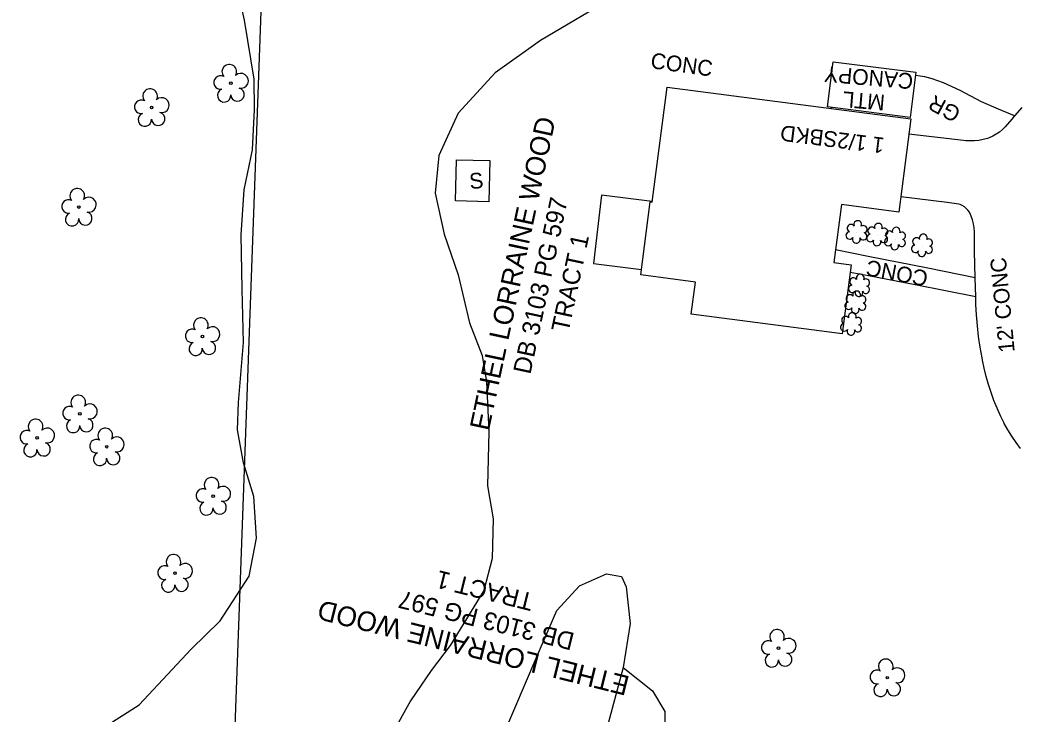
# Model space of a CAD drawing. Extents: x 1614611 to 1617571, y 898867 to 905462.
# Drawn here: x 1616188.4 to 1616442, y 900981.3 to 901157.4 of the extents above; entities that cross this region are included whole.
import ezdxf

# ---------------------------------------------------------------- set-up
doc = ezdxf.new("R2010")
doc.units = 0
for name, color, linetype in [('Exist Building', 7, 'Continuous'), ('Exist Building Metal Canopy', 7, 'Continuous'), ('Exist Building Metal Canopy Text', 7, 'Continuous'), ('Exist Building Text', 7, 'Continuous'), ('Exist Other Culture Area Outline', 7, 'Continuous'), ('Exist Other Culture Area Outline Text', 7, 'Continuous'), ('Exist Roads EOP Other Text', 7, 'Continuous'), ('Exist Roads Soil', 7, 'Continuous'), ('Exist Roads Soil Text', 7, 'Continuous'), ('Exist Vegetation Hedge Row', 7, 'Continuous'), ('Exist Vegetation Shrub CELL', 7, 'Continuous'), ('Exist Vegetation Tree CELL', 7, 'Continuous'), ('Exist Vegetation Woods Line', 7, 'Continuous'), ('Prop Drainage Structure Pipe Alternate 30in Label', 7, 'Continuous'), ('Prop Drainage Structure Pipe Removal', 7, 'Continuous'), ('Prop Drainage Structure Pipe Removal Label', 7, 'Continuous'), ('Scratch_Level_1', 7, 'Continuous')]:
    doc.layers.add(name, color=color, linetype=linetype)

msp = doc.modelspace()

# ---------------------------------------------------------------- linework, layer by layer
at = {"layer": 'Exist Building'}
for points in [[(1616396.84, 901077.74), (1616358.59, 901082.71), (1616359.65, 901090.88), (1616345.81, 901092.68), (1616348.22, 901111.22), (1616348.7, 901111.16), (1616352.48, 901140.3), (1616414.28, 901132.27), (1616411.21, 901108.63), (1616396.69, 901110.52), (1616394.79, 901095.84), (1616399.12, 901095.28)], [(1616307.51, 901121.72), (1616307.26, 901111.26), (1616298.82, 901111.46), (1616299.07, 901121.92)]]:
    msp.add_lwpolyline(points, close=True, dxfattribs=at)
at = {"layer": 'Exist Building Metal Canopy'}
msp.add_lwpolyline([(1616394.62, 901146.76), (1616415.59, 901144.12), (1616414.15, 901132.66), (1616393.18, 901135.29)], close=True, dxfattribs=at)
at = {"layer": 'Exist Other Culture Area Outline'}
for points in [[(1616348.72, 901111.35), (1616335.84, 901112.95), (1616334.83, 901104.27), (1616333.79, 901095.59), (1616345.99, 901094.11)], [(1616430.62, 901091.98), (1616418.63, 901094.43), (1616403.51, 901097.39), (1616395.21, 901099.09)], [(1616430.73, 901087.1), (1616415.4, 901090.19), (1616403.56, 901092.48), (1616398.87, 901093.33)]]:
    msp.add_lwpolyline(points, dxfattribs=at)
at = {"layer": 'Exist Roads Soil'}
for points in [[(1616440.58, 901133.01), (1616436.48, 901134.71), (1616432.24, 901136.61), (1616426.81, 901139.47), (1616422.54, 901141.46), (1616419.7, 901142.46), (1616417.85, 901142.91), (1616415.49, 901143.31)], [(1616394.15, 901135.17), (1616394.11, 901134.89)]]:
    msp.add_lwpolyline(points, dxfattribs=at)
at = {"layer": 'Exist Vegetation Hedge Row'}
msp.add_lwpolyline([(1616341.37, 900993.14), (1616348.75, 900987.2), (1616351.92, 900981.98), (1616351.91, 900977.26)], dxfattribs=at)
at = {"layer": 'Exist Vegetation Shrub CELL'}
for p, q in [((1616400.59, 901103.42), (1616400.59, 901103.42)), ((1616405.83, 901102.75), (1616405.83, 901102.75)), ((1616410.34, 901101.75), (1616410.34, 901101.75)), ((1616417.2, 901100.03), (1616417.2, 901100.03)), ((1616401.24, 901089.87), (1616401.24, 901089.87)), ((1616400.31, 901085.59), (1616400.31, 901085.59)), ((1616399.21, 901080.09), (1616399.21, 901080.09))]:
    msp.add_line(p, q, dxfattribs=at)
for centre, radius, start, end in [((1616399.11, 901104.54), 0.968, 35.8908, 245.4216), ((1616400.82, 901105.46), 0.99, 334.8391, 200.4717), ((1616406.06, 901104.79), 0.99, 334.8391, 200.4717), ((1616398.79, 901102.71), 0.955, 95.1099, 327.9534), ((1616402.23, 901102.49), 0.937, 204.9913, 73.4601), ((1616402.26, 901104.28), 0.929, 284.4567, 126.0861), ((1616404.03, 901102.05), 0.955, 95.1099, 327.9534), ((1616404.35, 901103.88), 0.968, 35.8908, 245.4216), ((1616407.5, 901103.62), 0.929, 284.4567, 126.0861), ((1616408.85, 901102.88), 0.968, 35.8908, 245.4216), ((1616410.57, 901103.79), 0.99, 334.8391, 200.4717), ((1616412.01, 901102.62), 0.929, 284.4567, 126.0861), ((1616417.43, 901102.07), 0.99, 334.8391, 200.4717), ((1616400.46, 901101.73), 0.984, 151.2797, 21.387), ((1616405.7, 901101.07), 0.984, 151.2797, 21.387), ((1616407.47, 901101.82), 0.937, 204.9913, 73.4601), ((1616408.54, 901101.05), 0.955, 95.1099, 327.9534), ((1616410.21, 901100.07), 0.984, 151.2797, 21.387), ((1616411.97, 901100.82), 0.937, 204.9913, 73.4601), ((1616415.4, 901099.33), 0.955, 95.1099, 327.9534), ((1616415.71, 901101.16), 0.968, 35.8908, 245.4216), ((1616418.87, 901100.9), 0.929, 284.4567, 126.0861), ((1616417.07, 901098.35), 0.984, 151.2797, 21.387), ((1616418.83, 901099.1), 0.937, 204.9913, 73.4601), ((1616401.47, 901091.91), 0.99, 334.8391, 200.4717), ((1616399.44, 901089.16), 0.955, 95.1099, 327.9534), ((1616399.76, 901091), 0.968, 35.8908, 245.4216), ((1616402.91, 901090.74), 0.929, 284.4567, 126.0861), ((1616398.83, 901086.71), 0.968, 35.8908, 245.4216), ((1616400.54, 901087.63), 0.99, 334.8391, 200.4717), ((1616401.11, 901088.19), 0.984, 151.2797, 21.387), ((1616402.88, 901088.94), 0.937, 204.9913, 73.4601), ((1616398.51, 901084.88), 0.955, 95.1099, 327.9534), ((1616401.95, 901084.66), 0.937, 204.9913, 73.4601), ((1616401.98, 901086.46), 0.929, 284.4567, 126.0861), ((1616399.44, 901082.13), 0.99, 334.8391, 200.4717), ((1616400.18, 901083.9), 0.984, 151.2797, 21.387), ((1616397.41, 901079.39), 0.955, 95.1099, 327.9534), ((1616397.72, 901081.22), 0.968, 35.8908, 245.4216), ((1616400.84, 901079.16), 0.937, 204.9913, 73.4601), ((1616400.88, 901080.96), 0.929, 284.4567, 126.0861), ((1616399.08, 901078.41), 0.984, 151.2797, 21.387)]:
    msp.add_arc(centre, radius, start, end, dxfattribs=at)
at = {"layer": 'Exist Vegetation Tree CELL'}
for p, q in [((1616241.85, 901141.34), (1616241.85, 901141.34)), ((1616221.77, 901135.18), (1616221.77, 901135.18)), ((1616203.3, 901109.91), (1616203.3, 901109.91)), ((1616234.64, 901077.08), (1616234.64, 901077.08)), ((1616203.55, 901057.48), (1616203.55, 901057.48)), ((1616192.72, 901051.37), (1616192.72, 901051.37)), ((1616210.38, 901049.12), (1616210.38, 901049.12)), ((1616237.36, 901036.59), (1616237.36, 901036.59)), ((1616227.7, 901017.04), (1616227.7, 901017.04)), ((1616380.74, 900998.04), (1616380.74, 900998.04)), ((1616408.32, 900990.56), (1616408.32, 900990.56))]:
    msp.add_line(p, q, dxfattribs=at)
for centre in [(1616241.85, 901141.34), (1616221.77, 901135.18), (1616203.3, 901109.91), (1616234.64, 901077.08), (1616203.55, 901057.48), (1616192.72, 901051.37), (1616210.38, 901049.12), (1616237.36, 901036.59), (1616227.7, 901017.04), (1616380.74, 900998.04), (1616408.32, 900990.56)]:
    msp.add_circle(centre, 0.326, dxfattribs=at)
for centre, radius, start, end in [((1616241.47, 901144.21), 1.86, 330.1651, 219.7134), ((1616244.4, 901141.93), 1.9, 257.1011, 134.1999), ((1616239.25, 901141.49), 1.73, 62.6636, 279.3457), ((1616221.38, 901138.05), 1.86, 330.1651, 219.7134), ((1616240.15, 901138.22), 1.69, 111.5671, 6.231), ((1616243.53, 901138.44), 1.7, 181.2822, 74.56), ((1616219.16, 901135.33), 1.73, 62.6636, 279.3457), ((1616224.32, 901135.76), 1.9, 257.1011, 134.1999), ((1616220.06, 901132.06), 1.69, 111.5671, 6.231), ((1616223.44, 901132.28), 1.7, 181.2822, 74.56), ((1616202.91, 901112.78), 1.86, 330.1651, 219.7134), ((1616200.69, 901110.06), 1.73, 62.6636, 279.3457), ((1616205.84, 901110.5), 1.9, 257.1011, 134.1999), ((1616201.59, 901106.79), 1.69, 111.5671, 6.231), ((1616204.97, 901107.01), 1.7, 181.2822, 74.56), ((1616234.25, 901079.96), 1.86, 330.1651, 219.7134), ((1616232.03, 901077.24), 1.73, 62.6636, 279.3457), ((1616237.19, 901077.67), 1.9, 257.1011, 134.1999), ((1616232.94, 901073.96), 1.69, 111.5671, 6.231), ((1616236.31, 901074.19), 1.7, 181.2822, 74.56), ((1616203.16, 901060.36), 1.86, 330.1651, 219.7134), ((1616206.1, 901058.07), 1.9, 257.1011, 134.1999), ((1616200.94, 901057.64), 1.73, 62.6636, 279.3457), ((1616192.34, 901054.25), 1.86, 330.1651, 219.7134), ((1616201.85, 901054.36), 1.69, 111.5671, 6.231), ((1616205.22, 901054.58), 1.7, 181.2822, 74.56), ((1616190.12, 901051.53), 1.73, 62.6636, 279.3457), ((1616195.27, 901051.96), 1.9, 257.1011, 134.1999), ((1616210, 901051.99), 1.86, 330.1651, 219.7134), ((1616191.02, 901048.25), 1.69, 111.5671, 6.231), ((1616194.4, 901048.47), 1.7, 181.2822, 74.56), ((1616207.78, 901049.27), 1.73, 62.6636, 279.3457), ((1616212.93, 901049.71), 1.9, 257.1011, 134.1999), ((1616208.68, 901046), 1.69, 111.5671, 6.231), ((1616212.06, 901046.22), 1.7, 181.2822, 74.56), ((1616236.98, 901039.46), 1.86, 330.1651, 219.7134), ((1616234.75, 901036.74), 1.73, 62.6636, 279.3457), ((1616239.91, 901037.18), 1.9, 257.1011, 134.1999), ((1616235.66, 901033.47), 1.69, 111.5671, 6.231), ((1616239.03, 901033.69), 1.7, 181.2822, 74.56), ((1616227.31, 901019.92), 1.86, 330.1651, 219.7134), ((1616230.25, 901017.63), 1.9, 257.1011, 134.1999), ((1616225.09, 901017.2), 1.73, 62.6636, 279.3457), ((1616225.99, 901013.92), 1.69, 111.5671, 6.231), ((1616229.37, 901014.14), 1.7, 181.2822, 74.56), ((1616380.35, 901000.92), 1.86, 330.1651, 219.7134), ((1616378.13, 900998.2), 1.73, 62.6636, 279.3457), ((1616383.29, 900998.63), 1.9, 257.1011, 134.1999), ((1616379.03, 900994.92), 1.69, 111.5671, 6.231), ((1616382.41, 900995.15), 1.7, 181.2822, 74.56), ((1616407.93, 900993.43), 1.86, 330.1651, 219.7134), ((1616405.71, 900990.71), 1.73, 62.6636, 279.3457), ((1616410.87, 900991.15), 1.9, 257.1011, 134.1999), ((1616406.61, 900987.44), 1.69, 111.5671, 6.231), ((1616409.99, 900987.66), 1.7, 181.2822, 74.56)]:
    msp.add_arc(centre, radius, start, end, dxfattribs=at)
at = {"layer": 'Exist Vegetation Woods Line'}
for points in [[(1616247.81, 901142.31), (1616245.31, 901157.28), (1616242.53, 901169.98), (1616241.6, 901183.11), (1616236.73, 901194.27), (1616233.8, 901204.31), (1616233.81, 901212.27), (1616236.73, 901218.88), (1616241.22, 901222.24), (1616269.76, 901222.04), (1616317.07, 901221.97), (1616350.48, 901216.77), (1616404.41, 901201.78), (1616411.14, 901194.75), (1616412.67, 901183.9), (1616411.12, 901177.78), (1616404.34, 901171.48), (1616396.18, 901169.07), (1616361.18, 901167.41), (1616339.54, 901163.57), (1616320.37, 901152.12), (1616308.92, 901143.99)], [(1616308.92, 901143.99), (1616299.53, 901133.71), (1616294.6, 901122.96), (1616293.66, 901113.43), (1616295.95, 901103.06), (1616299.46, 901092.74), (1616302.35, 901080.56), (1616305.55, 901072.27), (1616306.65, 901065.61), (1616307.31, 901052.94), (1616306.94, 901039.19), (1616308.39, 901030.83), (1616308.09, 901020.79), (1616306.01, 901012.65), (1616297.5, 900998.71), (1616292.65, 900992.36), (1616287.41, 900984.68), (1616282.65, 900976.17)], [(1616205.76, 900975.49), (1616218.57, 900983.63), (1616226.97, 900992.63), (1616231.77, 900997.75), (1616239.14, 901004.95), (1616246.52, 901016.28), (1616248.4, 901025.93), (1616247.67, 901036.5), (1616245.1, 901045.02), (1616243.51, 901053.41), (1616243.8, 901060.34), (1616245.05, 901075.6), (1616244.76, 901089.06), (1616244.5, 901102.86), (1616245.23, 901114.27), (1616247.34, 901124.44), (1616247.85, 901134.66), (1616247.81, 901142.31)], [(1616310.9, 900975.9), (1616319.26, 900995.52), (1616324.56, 901007.61), (1616330.28, 901013.87), (1616337.14, 901016.9), (1616340.93, 901016.24), (1616342.1, 901013.57), (1616343.11, 901004.29), (1616341.37, 900993.14), (1616337.61, 900979.23)]]:
    msp.add_lwpolyline(points, dxfattribs=at)
at = {"layer": 'Prop Drainage Structure Pipe Alternate 30in Label'}
msp.add_lwpolyline([(1616242.67, 900971.23), (1616252.26, 901234.03)], dxfattribs=at)
at = {"layer": 'Scratch_Level_1'}
for points in [[(1616442.45, 901135.2), (1616440.58, 901133.01), (1616440.51, 901132.93), (1616439.9, 901132.21), (1616438.22, 901130.25), (1616437.5, 901129.56), (1616436.73, 901128.94), (1616435.92, 901128.38), (1616435.06, 901127.89), (1616434.16, 901127.47), (1616433.75, 901127.31), (1616432.66, 901127.03), (1616431.57, 901126.83), (1616430.46, 901126.71), (1616429.34, 901126.67), (1616428.22, 901126.71), (1616427.68, 901126.76), (1616413.78, 901128.36)], [(1616442.1, 901048.71), (1616440.97, 901050.23), (1616439.91, 901051.79), (1616438.92, 901053.4), (1616437.99, 901055.05), (1616437.99, 901055.06), (1616437.03, 901056.96), (1616436.15, 901058.9), (1616435.35, 901060.88), (1616434.62, 901062.88), (1616433.96, 901064.91), (1616433.38, 901066.96), (1616432.88, 901069.03), (1616432.45, 901071.12), (1616432.36, 901071.65), (1616431.88, 901074.36), (1616431.48, 901077.08), (1616431.17, 901079.81), (1616430.93, 901082.55), (1616430.77, 901085.23), (1616430.73, 901087.1), (1616430.62, 901091.98), (1616430.46, 901098.61), (1616430.42, 901102.58), (1616430.42, 901103.6), (1616430.33, 901104.62), (1616430.17, 901105.64), (1616429.93, 901106.64), (1616429.61, 901107.62), (1616429.44, 901108.04), (1616429.14, 901108.59), (1616428.77, 901109.1), (1616428.34, 901109.56), (1616427.86, 901109.96), (1616427.33, 901110.3), (1616426.76, 901110.57), (1616426.44, 901110.68), (1616423.46, 901111.11), (1616411.71, 901112.48)]]:
    msp.add_lwpolyline(points, dxfattribs=at)

# ---------------------------------------------------------------- texts
at = {"layer": 'Exist Building Metal Canopy Text'}
for s, p in [('CANOPY', (1616415.02, 901143.76)), ('MTL ', (1616407.86, 901138.35))]:
    msp.add_text(s, height=4, rotation=175.1049, dxfattribs=at).set_placement(p)
at = {"layer": 'Exist Building Text'}
for s, rotation, p in [('1 1/2SBKD', 172.8762, (1616407.73, 901127.45)), ('S', 5.2866, (1616302.5, 901114.44))]:
    msp.add_text(s, height=4, rotation=rotation, dxfattribs=at).set_placement(p)
at = {"layer": 'Exist Other Culture Area Outline Text'}
for rotation, p in [(352.1085, (1616348.12, 901145.16)), (169.3406, (1616418.89, 901093.65))]:
    msp.add_text('CONC', height=4, rotation=rotation, dxfattribs=at).set_placement(p)
at = {"layer": 'Exist Roads EOP Other Text'}
msp.add_text("12' CONC", height=4, rotation=95.4108, dxfattribs=at).set_placement((1616440.64, 901073.21))
at = {"layer": 'Exist Roads Soil Text'}
msp.add_text('GR', height=4, rotation=152.1709, dxfattribs=at).set_placement((1616427.27, 901134.74))
at = {"layer": 'Prop Drainage Structure Pipe Removal'}
for rotation, p in [(77.8966, (1616307.28, 901052.97)), (166.067, (1616343.26, 900990.81))]:
    msp.add_text('ETHEL LORRAINE WOOD', height=5, rotation=rotation, dxfattribs=at).set_placement(p)
at = {"layer": 'Prop Drainage Structure Pipe Removal Label'}
for s, rotation, p in [('DB 3103 PG 597', 77.9111, (1616317.8, 901067.3)), ('TRACT 1', 77.9111, (1616327.47, 901077.94)), ('TRACT 1', 166.0815, (1616318.95, 901011.79)), ('DB 3103 PG 597', 166.0815, (1616329.27, 901001.79))]:
    msp.add_text(s, height=4.5, rotation=rotation, dxfattribs=at).set_placement(p)

doc.saveas('drawing.dxf')
